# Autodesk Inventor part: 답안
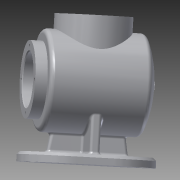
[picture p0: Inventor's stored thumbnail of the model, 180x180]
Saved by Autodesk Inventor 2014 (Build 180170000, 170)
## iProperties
Created: 2016-04
Part Number: 답안
Material: 알루미늄 6061
Document SubType Name: Modeling
Designer: owner
Density: 2.71 g/cm^3
Appearance: 알루미늄 - 평지
Mass: 908.091 g
Surface Area: 1234.91 cm^2
Volume: 335.089 cm^3
Author: owner
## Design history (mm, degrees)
sketch "스케치1"
  geometry: C1 r 50 at (0, 0); 1 further point
  constraints: 1 centre point, 1 coincident
  dimensions: "d0" = 100 diameter of C1
extrude "돌출1" new body sketch "스케치1" distance "d1" = 110; taper "d2" = 0 deg
sketch "스케치2"
  geometry: C1 r 50 at (0, 0) reference; C2 r 38 at (0, 0)
  constraints: 1 centre point, 1 coincident
  dimensions: "d3" = 76 diameter of C2
extrude "돌출2" join sketch "스케치2" distance "d4" = 12; taper "d5" = 0 deg
sketch "스케치3"
  geometry: L1 (50, 110)-(-50, 110) reference; L2 (-50, 0)-(50, 0) reference; L3 (38, 122)-(-38, 122) reference; L4 (-38, 110)-(38, 110) reference; L5 (50, 0)-(50, 110) reference; L6 (50, 10.717)-(50, 0); A1 r 122 centre (0, 122) between (0, 0) and (50, 10.717); 2 further points
  constraints: 3 point on circle, 2 end point, 2 midpoint, 1 centre point, 1 collinear, 1 point on line, 1 vertical, 1 vertical alignment, 2 other
revolve "회전1" sketch "스케치3" stored, may be unused: angle "d6" = 90 deg
sketch "스케치4"
  geometry: L1 (50, 10.717)-(50, 110) reference; L2 (-50, 10.717)-(-50, 110) reference; L3 (50, 110)-(-50, 110) reference; L4 (47, 12.675)-(47, 107); L5 (47, 107)-(0, 107); L6 (0, 122)-(0, -8.698); A1 r 122 centre (0, 122) between (-50, 10.717) and (50, 10.717) reference; A2 r 119 centre (0, 122) between (0, 3) and (47, 12.675); 1 further point
  constraints: 6 end point, 2 point on circle, 2 point on line, 1 centre point
  dimensions: "d7" = 3 distance between parallel lines of L1 L4; "d8" = 3 radial gap between concentric circles of A1 A2
revolve "회전2" sketch "스케치4" stored, may be unused: angle "d9" = 90 deg
sketch "스케치5"
  geometry: C1 r 38 at (0, 0) reference; C2 r 27 at (0, 0)
  constraints: 1 centre point, 1 coincident
  dimensions: "d10" = 54 diameter of C2
extrude "돌출3" cut sketch "스케치5" distance "d11" = 25; taper "d12" = 0 deg
node "작업 평면2"
  node "작업 평면1"
sketch "스케치6"
  geometry: L1 (50, 10.717)-(-50, 10.717) reference; L2 (50, 110)-(-50, 110) reference; L3 (50, 10.717)-(50, 110) reference; C1 r 38 at (0, 60.358); 2 further points
  constraints: 1 centre point, 1 horizontal alignment, 1 midpoint, 1 vertical alignment
  dimensions: "d14" = 76 diameter of C1
extrude "돌출4" join sketch "스케치6" stored distance "d15" = 25; taper "d16" = 0 deg
sketch "스케치7"
  geometry: C1 r 38 at (0, 0) reference; C2 r 27 at (0, 0); 1 further point
  constraints: 1 centre point, 1 coincident
  dimensions: "d17" = 54 diameter of C2
extrude "돌출5" cut sketch "스케치7" distance "d18" = 25; taper "d19" = 0 deg
sketch "스케치8"
  geometry: L1 (-69, 127.858)-(-79, 127.858); L2 (-79, 127.858)-(-79, -7.142); L3 (-79, -7.142)-(-69, -7.142); L4 (-69, -7.142)-(-69, 127.858); L5 (-50, 10.717)-(-50, 110) reference; L6 (65, 98.358)-(65, 22.358) reference; L7 (50, 10.717)-(50, 110) reference; L8 (-69, 100.358)-(-50, 97.008); L9 (-69, 20.358)-(-48.684, 23.941); L10 (-50, 97.008)-(-48.684, 96.776); L11 (-48.684, 96.776)-(-48.684, 23.941); 3 further points
  constraints: 16 end point, 3 parallel, 3 point on line, 2 midpoint, 1 collinear, 1 horizontal, 1 horizontal alignment, 1 perpendicular
  dimensions: "d20" = 135 distance of L1.end L2.end; "d21" = 10 distance of L2.end L3.end; "d22" = 79 distance from line of L2 point (0, 0); "d23" = 40 distance of L8.start point (-69, 60.358); "d24" = 40 distance of L9.start point (-69, 60.358); "d25" = 100 deg angle of L4 L8; "d26" = 100 deg angle of L4 L9
extrude "돌출6" join sketch "스케치8" stored distance "d27" = 100; taper "d28" = 0 deg
extrude "돌출7" join sketch "스케치8" stored distance "d29" = 10; taper "d30" = 0 deg
node "작업 평면3"
sketch "스케치9"
  geometry: L1 (100, -10)-(0, -10) reference; L2 (0, 0)-(0, -10) reference; L3 (0, 0)-(100, 0) reference; L4 (100, -10)-(100, 0) reference; L5 (10, 0)-(10, 39); L6 (90, 0)-(90, 39); L7 (55, 0)-(55, 19.251) reference; L8 (45, 0)-(55, 0) reference; L9 (45, 19.251)-(45, 0) reference; A1 r 50 centre (50, 69) between (10, 39) and (90, 39) reference; A2 r 50 centre (50, 69) between (45, 19.251) and (55, 19.251) reference; 1 further point
  constraints: 4 end point, 3 parallel, 2 point on circle, 2 point on line
  dimensions: "d31" = 40 distance from line of point (50, 69) L5
  node "투영된 루프4"
  node "투영된 루프5"
feature "리브1" dims "d32" = 1, "d33" = 10, "d34" = 0, "d35" = 0, "d36" = 1, "d37" = 1
feature "리브2" dims "d38" = 1, "d39" = 10, "d40" = 0, "d41" = 0, "d42" = 1, "d43" = 1
sketch "스케치10"
  geometry: L1 (100, -135)-(100, 0) reference; L2 (0, -135)-(100, -135) reference; L3 (0, 0)-(0, -135) reference; L4 (0, 0)-(100, 0) reference; L5 (100, -67.5)-(0, -67.5); C1 r 5 at (50, -13.5); C2 r 5 at (50, -121.5); 1 further point
  constraints: 2 centre point, 2 end point, 2 midpoint
  dimensions: "d44" = 10 diameter of C1; "d45" = 10 diameter of C2; "d46" = 54 distance from line of L5 C1.centre; "d47" = 54 distance from line of L5 C2.centre
extrude "돌출8" cut sketch "스케치10" distance "d48" = 10; taper "d49" = 0 deg
fillet "모깎기1" dims "d50" = 50
sketch "스케치11"
  geometry: C1 r 27 at (0, 0) reference; 1 further point
  constraints: 1 vertical alignment
  dimensions: "d51" = 32.5 distance of C1.centre point (0, 32.5)
hole "구멍1" sketch "스케치11" at (0, 32.5) diameter "d52" = 3.242; stored, may be unused: countersink angle "d56" = 90 deg, drill point angle "d58" = 118 deg; dims "d53" = 8, "d54" = 4, "d55" = 2, "d57" = 10
sketch "스케치12"
  geometry: C1 r 38 at (0, 0) reference; 2 further points
  constraints: 1 vertical alignment
  dimensions: "d62" = 32.5 distance of C1.centre point (0, 32.5)
hole "구멍2" sketch "스케치12" at (0, 32.5) diameter "d63" = 3.242; stored, may be unused: countersink angle "d67" = 90 deg, drill point angle "d69" = 118 deg; dims "d64" = 8, "d65" = 4, "d66" = 2, "d68" = 10
node "작업 평면4"
sketch "스케치13"
  geometry: L1 (50, -79)-(-50, -79) reference; 2 further points
  constraints: 2 coincident, 1 other
feature "엠보싱1" sketch "스케치13" dims "d74" = 0.5, "d75" = 0
fillet "모깎기2" dims "d76" = 5
fillet "모깎기3" dims "d77" = 5
chamfer "모따기1" distance "d78" = 1; stored, may be unused: second distance "d79" = 2, angle "d80" = 45 deg
fillet "모깎기4" dims "d81" = 3
fillet "모깎기5" dims "d82" = 3
fillet "모깎기6" dims "d83" = 3
fillet "모깎기7" dims "d84" = 3
fillet "모깎기8" dims "d85" = 3
fillet "모깎기9" dims "d86" = 3
fillet "모깎기10" dims "d87" = 2
fillet "모깎기11" dims "d88" = 2
chamfer "모따기2" distance "d90" = 3; stored, may be unused: second distance "d91" = 2, angle "d92" = 45 deg
node "솔리드1"
pattern_circular "원형 패턴1" dims angle "d60" = 360 deg
pattern_circular "원형 패턴2" dims angle "d71" = 360 deg
node "투영된 루프1"
node "투영된 루프2"
node "투영된 루프3"
node "투영된 루프6"
other parameters: "d13" = 15
